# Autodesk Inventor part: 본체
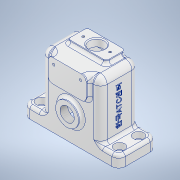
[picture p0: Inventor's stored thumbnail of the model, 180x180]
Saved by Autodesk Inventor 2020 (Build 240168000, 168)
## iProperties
Created: 2023-12
Part Number: 본체
Material: 알루미늄 6061
Document SubType Name: Modeling
Designer: oem
Density: 2.7 g/cm^3
Appearance: 알루미늄 - 평지
Mass: 219.842 g
Surface Area: 358.807 cm^2
Volume: 81.4231 cm^3
Author: oem
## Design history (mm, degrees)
sketch "스케치2"
  geometry: L1 (50, 20)-(-50, 20); L2 (-50, 20)-(-50, -20); L3 (-50, -20)-(50, -20); L4 (50, -20)-(50, 20); L5 (50, 20)-(-50, -20); L6 (-50, 20)-(50, -20); 1 further point
  constraints: 12 end point, 2 midpoint, 2 parallel, 1 horizontal, 1 perpendicular
  dimensions: "d0" = 100 distance of L2.end L3.end; "d1" = 40 distance of L3.end L1.start
extrude "돌출1" new body sketch "스케치2" distance "d2" = 12; taper "d3" = 0 deg
sketch "스케치3"
  geometry: L1 (-31, 72)-(31, 72); L2 (31, 72)-(31, 0); L3 (31, 0)-(-31, 0); L4 (-31, 0)-(-31, 72); L5 (50, 0)-(-50, 0) reference; 2 further points
  constraints: 8 end point, 2 parallel, 1 coincident, 1 horizontal, 1 midpoint, 1 perpendicular
  dimensions: "d4" = 62 distance of L1.start L1.end; "d5" = 72 distance between parallel lines of L5 L1
extrude "돌출2" join sketch "스케치3" stored distance "d6" = 40; taper "d7" = 0 deg
sketch "스케치4"
  geometry: L1 (0, 0)-(100, 0) reference; L2 (81, 72)-(19, 72) reference; L3 (30, 72)-(70, 72); L4 (70, 72)-(70, 48); L5 (70, 48)-(30, 48); L6 (30, 48)-(30, 72); C1 r 12 at (50, 28); 5 further points
  constraints: 8 end point, 3 midpoint, 2 parallel, 2 vertical alignment, 1 centre point, 1 horizontal, 1 perpendicular, 1 point on line
  dimensions: "d8" = 24 diameter of C1; "d9" = 28 distance of point (50, 0) C1.centre; "d10" = 40 distance between parallel lines of L4 L6; "d11" = 24 distance between parallel lines of L5 L2
extrude "돌출3" join sketch "스케치4" distance "d12" = 4; taper "d13" = 0 deg
sketch "스케치5"
  geometry: C1 r 12 at (50, 28) reference; C2 r 20 at (50, 28); 1 further point
  constraints: 1 centre point, 1 coincident
  dimensions: "d14" = 40 diameter of C2
extrude "돌출4" join sketch "스케치5" distance "d15" = 4; taper "d16" = 0 deg
sketch "스케치6"
  geometry: L1 (51, -44)-(11, -44) reference; L2 (11, -3)-(51, -3); L3 (51, -3)-(51, -23); L4 (51, -23)-(11, -23); L5 (11, -23)-(11, -3); L6 (11, -13)-(51, -13); 2 further points
  constraints: 10 end point, 3 midpoint, 2 parallel, 1 horizontal, 1 perpendicular, 1 vertical alignment
  dimensions: "d18" = 20 distance between parallel lines of L4 L2; "d19" = 40 distance of L2.start L2.end; "d20" = 31 distance between parallel lines of L1 L6
extrude "돌출5" join sketch "스케치6" distance "d21" = 4; taper "d22" = 0 deg
sketch "스케치7"
  geometry: C1 r 12 at (0, 0) reference; 2 further points
  constraints: 1 coincident
hole "구멍1" sketch "스케치7" at (0, 0) diameter "d23" = 14.91747; stored, may be unused: countersink angle "d27" = 90 deg, drill point angle "d29" = 0 deg; dims "d24" = 20, "d25" = 4, "d26" = 2, "d28" = 20
sketch "스케치8"
  geometry: L1 (-31, 12)-(-31, 72) reference; L2 (-31, 72)-(31, 72) reference; L3 (31, 72)-(31, 12) reference; L4 (27, 0)-(27, 68); L5 (27, 68)-(-27, 68); L6 (-27, 68)-(-27, 0); L7 (50, 0)-(-50, 0) reference; L8 (-27, 0)-(27, 0); 1 further point
  constraints: 8 end point, 2 point on line, 1 collinear
  dimensions: "d30" = 4 distance between parallel lines of L2 L5
extrude "돌출6" cut sketch "스케치8" stored distance "d31" = 32; taper "d32" = 0 deg
sketch "스케치9"
  geometry: C1 r 20 at (0, 0) reference; C2 r 9 at (0, 0); 1 further point
  constraints: 1 centre point, 1 coincident
  dimensions: "d33" = 18 diameter of C2
extrude "돌출7" cut sketch "스케치9" distance "d34" = 10; taper "d35" = 0 deg
sketch "스케치10"
  geometry: C1 r 9 at (0, 0) reference; C2 r 20 at (0, 0) reference; A1 r 15 centre (0, 0) between (0, 15) and (15, 0); 3 further points
  constraints: 4 point on circle, 2 horizontal alignment, 2 vertical alignment, 1 centre point, 1 coincident
  dimensions: "d36" = 30 diameter of A1
hole "구멍2" sketch "스케치10" at (0, 15), (15, 0), (0, -15), (-15, 0) diameter "d37" = 2.459; stored, may be unused: countersink angle "d41" = 90 deg, drill point angle "d43" = 0 deg; dims "d38" = 10, "d39" = 4, "d40" = 2, "d42" = 10
sketch "스케치11"
  geometry: L1 (70, 72)-(30, 72) reference; L2 (30, 48)-(70, 48) reference; L3 (70, 72)-(30, 72) reference; L4 (50, 72)-(50, 48); 3 further points
  constraints: 2 end point, 2 midpoint, 1 horizontal alignment
  dimensions: "d44" = 28 distance of point (64, 66) point (36, 66); "d45" = 14 distance from line of L4 point (36, 66); "d46" = 6 distance from line of point (36, 66) L1
hole "구멍3" sketch "스케치11" at (36, 66), (64, 66) diameter "d47" = 2.459; stored, may be unused: countersink angle "d51" = 90 deg, drill point angle "d53" = 0 deg; dims "d48" = 10, "d49" = 4, "d50" = 2, "d52" = 10
sketch "스케치12"
  geometry: L1 (51, -3)-(11, -3) reference; C1 r 8 at (31, -13); 1 further point
  constraints: 1 centre point
  dimensions: "d54" = 16 diameter of C1; "d55" = 10 distance from line of C1.centre L1
extrude "돌출8" cut sketch "스케치12" distance "d56" = 20; taper "d57" = 0 deg
sketch "스케치13"
  geometry: C1 r 8 at (31, -13) reference; 3 further points
  constraints: 2 horizontal alignment
  dimensions: "d58" = 28 distance of point (45, -13) point (17, -13); "d59" = 14 distance of C1.centre point (17, -13)
hole "구멍4" sketch "스케치13" at (17, -13), (45, -13) diameter "d60" = 2.459; stored, may be unused: countersink angle "d64" = 90 deg, drill point angle "d66" = 0 deg; dims "d61" = 20, "d62" = 4, "d63" = 2, "d65" = 20
sketch "스케치14"
  geometry: L1 (-41, -10)-(41, -10); L2 (41, -10)-(41, 10); L3 (41, 10)-(-41, 10); L4 (-41, 10)-(-41, -10); L5 (-41, -10)-(41, 10); L6 (41, -10)-(-41, 10); C1 r 5.5 at (-41, 10); C2 r 5.5 at (-41, -10); C3 r 5.5 at (41, 10); C4 r 5.5 at (41, -10); 1 further point
  constraints: 12 end point, 4 centre point, 4 coincident, 2 midpoint, 2 parallel, 1 horizontal, 1 perpendicular
  dimensions: "d67" = 82 distance of L2.end L3.end; "d68" = 20 distance between parallel lines of L1 L3; "d69" = 11 diameter of C1; "d70" = 11 diameter of C2; "d71" = 11 diameter of C3; "d72" = 11 diameter of C4
extrude "돌출9" cut sketch "스케치14" distance "d73" = 6.6; taper "d74" = 0 deg
sketch "스케치17"
  geometry: C1 r 5.5 at (41, -10) reference; C2 r 5.5 at (-41, 10) reference; C3 r 5.5 at (-41, -10) reference; C4 r 3.3 at (-41, 10); C5 r 3.3 at (-41, -10); C6 r 5.5 at (41, 10) reference; C7 r 3.3 at (41, 10); C8 r 3.3 at (41, -10); 1 further point
  constraints: 4 centre point, 4 coincident
  dimensions: "d75" = 6.6 diameter of C4; "d76" = 6.6 diameter of C5; "d77" = 6.6 diameter of C7; "d78" = 6.6 diameter of C8
extrude "돌출10" cut sketch "스케치17" distance "d79" = 20; taper "d80" = 0 deg
fillet "모깎기1" dims "d81" = 7
fillet "모깎기4" dims "d84" = 7
fillet "모깎기14" dims "d94" = 3
fillet "모깎기15" dims "d95" = 3
fillet "모깎기16" dims "d96" = 3
fillet "모깎기17" dims "d97" = 3
chamfer "모따기1" distance "d98" = 1; stored, may be unused: second distance "d99" = 2, angle "d100" = 45 deg
fillet "모깎기18" dims "d101" = 3
fillet "모깎기19" dims "d102" = 3
fillet "모깎기21" dims "d104" = 7
fillet "모깎기22" dims "d105" = 7
fillet "모깎기23" dims "d106" = 5
fillet "모깎기24" dims "d107" = 3
fillet "모깎기25" dims "d108" = 5
fillet "모깎기26" dims "d109" = 3
fillet "모깎기27" dims "d110" = 3
node "작업 평면1"
sketch "스케치18"
  geometry: L1 (0, -20)-(0, -13) reference; L2 (40, 24)-(16, 24) reference; 2 further points
  constraints: 1 other
  dimensions: "d112" = 40 distance from line of L1 point (40, 1); "d116" = 23 distance from line of point (40, 1) L2
feature "엠보싱1" sketch "스케치18" dims "d113" = 0.5, "d114" = 0
node "솔리드1"
feature "A9D066F2-1C7D-4E18-AEED-F7BC21143FA4" dims "d23" = 14.91747, "d24" = 20, "d25" = 4, "d26" = 2, "d27" = 90 deg, "d28" = 20, "d29" = 0
